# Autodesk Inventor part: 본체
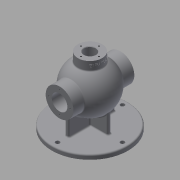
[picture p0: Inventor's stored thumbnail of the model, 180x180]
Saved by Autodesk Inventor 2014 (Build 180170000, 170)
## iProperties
Created: 2020-08
Part Number: 본체
Material: Generic
Document SubType Name: Modeling
Designer: kh
Density: 1 g/cm^3
Appearance: Default
Author: kh
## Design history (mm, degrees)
sketch "Sketch1"
  geometry: C1 r 85 at (0, 0); 1 further point
  constraints: 1 centre point, 1 coincident
  dimensions: "d0" = 170 diameter of C1
extrude "Extrusion1" new body sketch "Sketch1" distance "d1" = 10; taper "d2" = 0 deg
sketch "Sketch2"
  geometry: L1 (85, 10)-(85, 0) reference; L2 (85, 0)-(-85, 0) reference; L3 (-85, 0)-(-85, 10) reference; L4 (-85, 10)-(85, 10) reference; L5 (85, 10)-(85, 0) reference; L6 (85, 0)-(-85, 0) reference; L7 (-85, 0)-(-85, 10) reference; L8 (-85, 10)-(85, 10) reference; L9 (0, 0)-(0, 85); L10 (-68, 85)-(68, 85); L11 (42.988, 116)-(68, 116); L12 (0, 85)-(0, 138); L13 (68, 116)-(68, 102.5); L14 (68, 102.5)-(39.278, 102.5); L15 (-42.988, 116)-(-68, 116); L16 (-68, 116)-(-68, 102.5); L17 (-68, 102.5)-(-39.278, 102.5); A1 r 53 centre (0, 85) between (42.988, 116) and (0, 138); A2 r 43 centre (0, 85) between (39.278, 102.5) and (0, 128); A3 r 43 centre (0, 85) between (0, 128) and (-39.278, 102.5); A4 r 53 centre (0, 85) between (0, 138) and (-42.988, 116)
  constraints: 18 end point, 8 point on circle, 4 centre point, 4 perpendicular, 4 symmetric about line, 3 coincident, 2 parallel, 1 midpoint, 1 point on line, 1 vertical alignment, 2 other
  dimensions: "d3" = 85 distance of L9.end L9.start; "d4" = 53 radius of A1; "d5" = 43 radius of A2; "d7" = 62 diameter of L11.end L10; "d8" = 35 diameter of L13.end L10; "d9" = 136 distance of L10.start L10.end
revolve "Revolution1" sketch "Sketch2" stored, may be unused: angle "d15" = 90 deg
workplane "Work Plane1"
sketch "Sketch4"
  geometry: L1 (31, -42.988)-(-31, -42.988) reference; L2 (31, 42.988)-(-31, 42.988) reference; C1 r 27 at (0, 0); A1 r 53 centre (0, 0) between (-31, 42.988) and (31, 42.988) reference; 1 further point
  constraints: 1 centre point, 1 coincident
  dimensions: "d25" = 54 diameter of C1
extrude "Extrusion2" join sketch "Sketch4" stored distance "d26" = 10; taper "d27" = 0 deg
sketch "Sketch5"
  geometry: C1 r 27 at (0, 0) reference; C2 r 13 at (0, 0); 1 further point
  constraints: 1 centre point, 1 coincident
  dimensions: "d28" = 26 diameter of C2
extrude "Extrusion3" cut sketch "Sketch5" stored distance "d29" = 10; taper "d30" = 0 deg
sketch "Sketch6"
  geometry: L1 (0, 27)-(0, -27); L2 (27, 0)-(-27, 0); C1 r 13 at (0, 0) reference; A1 r 27 centre (0, 0) between (0, 27) and (0, -27) reference; A2 r 20 centre (0, 0) between (20, 0) and (0, 20); 6 further points
  constraints: 7 point on circle, 5 midpoint, 4 end point, 4 point on line, 1 centre point, 1 coincident, 1 horizontal, 1 horizontal alignment, 1 vertical, 1 other
  dimensions: "d31" = 40 diameter of A2
hole "Hole1" sketch "Sketch6" at (20, 0), (0, 20), (-20, 0), (0, -20) diameter "d32" = 3.242; stored, may be unused: countersink angle "d36" = 90 deg, drill point angle "d38" = 118 deg; dims "d33" = 12, "d34" = 4, "d35" = 2, "d37" = 15
sketch "Sketch7"
  geometry: L1 (-51, -85)-(-51, -75) reference; L2 (-51, -75)-(51, -75) reference; L3 (51, -75)-(51, -85) reference; L4 (51, -85)-(-51, -85) reference; L5 (0, 31)-(0, -31); L6 (-31, 0)-(31, 0); C1 r 17.5 at (0, 0) reference; A1 r 31 centre (0, 0) between (0, 31) and (0, -31) reference; A2 r 24 centre (0, 0) between (-24, 0) and (0, 24); 5 further points
  constraints: 8 point on circle, 4 end point, 4 midpoint, 4 point on line, 2 perpendicular, 1 centre point, 1 coincident
  dimensions: "d39" = 48 diameter of A2
hole "Hole2" sketch "Sketch7" at (-24, 0), (0, 24), (24, 0), (0, -24) diameter "d40" = 3.242; stored, may be unused: countersink angle "d44" = 90 deg, drill point angle "d46" = 118 deg; dims "d41" = 12, "d42" = 4, "d43" = 2, "d45" = 15
mirror "Mirror1"
sketch "Sketch8"
  geometry: L1 (-4, 52)-(4, 52); L2 (4, 52)-(4, -52); L3 (4, -52)-(-4, -52); L4 (-4, -52)-(-4, 52); L5 (-4, 52)-(4, -52); L6 (4, 52)-(-4, -52); L7 (-43, 4)-(43, 4); L8 (43, 4)-(43, -4); L9 (43, -4)-(-43, -4); L10 (-43, -4)-(-43, 4); L11 (-43, 4)-(43, -4); L12 (43, 4)-(-43, -4); C1 r 85 at (0, 0) reference
  constraints: 24 end point, 4 midpoint, 4 parallel, 2 horizontal, 2 perpendicular
  dimensions: "d49" = 8 distance of L2.end L3.end; "d50" = 104 distance of L1.end L2.end; "d51" = 86 distance of L8.end L9.end; "d52" = 8 distance of L7.end L8.end
extrude "Extrusion4" join sketch "Sketch8" stored distance "d53" = 10; taper "d54" = 0 deg
sketch "Sketch9"
  geometry: L1 (-43, 4)-(-4, 4) reference; L2 (-4, 4)-(-4, 52) reference; L3 (-4, 52)-(4, 52) reference; L4 (4, 52)-(4, 4) reference; L5 (4, 4)-(43, 4) reference; L6 (43, 4)-(43, -4) reference; L7 (43, -4)-(4, -4) reference; L8 (4, -4)-(4, -52) reference; L9 (4, -52)-(-4, -52) reference; L10 (-4, -52)-(-4, -4) reference; L11 (-4, -4)-(-43, -4) reference; L12 (-43, -4)-(-43, 4) reference; L13 (0, 85)-(0, -85); L14 (85, 0)-(-85, 0); C1 r 4.5 at (0, 72.5); C2 r 4.5 at (72.5, 0); C3 r 4.5 at (0, -72.5); C4 r 4.5 at (-72.5, 0); A1 r 85 centre (0, 0) between (0, 85) and (0, -85) reference; A2 r 72.5 centre (0, 0) between (0, 72.5) and (72.5, 0); 2 further points
  constraints: 8 point on circle, 5 centre point, 4 end point, 4 point on line, 3 equal radius, 3 midpoint, 2 parallel, 1 coincident
  dimensions: "d55" = 145 diameter of A2; "d56" = 9 diameter of C1
extrude "Extrusion5" cut sketch "Sketch9" stored distance "d57" = 10; taper "d58" = 0 deg
workplane "Work Plane2"
sketch "Sketch10"
  geometry: L1 (-59.206, -31.786)-(59.206, -31.786); L2 (59.206, -31.786)-(59.206, 13.786); L3 (59.206, 13.786)-(-59.206, 13.786); L4 (-59.206, 13.786)-(-59.206, -31.786); L5 (-59.206, -31.786)-(59.206, 13.786); L6 (59.206, -31.786)-(-59.206, 13.786); L7 (-27, 0)-(-27, -19.393) reference; L8 (-27, 0)-(27, 0) reference; L9 (27, 0)-(27, -19.393) reference; L10 (-27, -19.393)-(27, -19.393) reference; 2 further points
  constraints: 4 end point, 1 midpoint, 2 other
  dimensions: "d59" = 9 distance from line of L8 point (0, -9); "d60" = 27 distance from line of L7 point (0, -9)
emboss "Emboss1" sketch "Sketch10" dims "d61" = 0.5, "d62" = 0
fillet "Fillet1" dims "d63" = 3
fillet "Fillet2" dims "d64" = 3
fillet "Fillet3" dims "d65" = 3
fillet "Fillet4" dims "d66" = 3
chamfer "Chamfer1" distance "d67" = 1; stored, may be unused: second distance "d68" = 2, angle "d69" = 45 deg
sketch "Sketch11"
  geometry: L1 (85, 7)-(85, 0) reference; L2 (85, 0)-(77, 0) reference; L3 (77, 0)-(77, 10) reference; L4 (77, 10)-(82, 10) reference; L5 (-82, 10)-(-77, 10) reference; L6 (-77, 10)-(-77, 0) reference; L7 (-77, 0)-(-85, 0) reference; L8 (-85, 0)-(-85, 7) reference; L9 (-52.026, 61)-(-53, 62.621) reference; L10 (-53, 62.621)-(-68, 62.621) reference; L11 (-68, 62.621)-(-68, 67.5) reference; L12 (-68, 67.5)-(-39.278, 67.5) reference; L13 (39.278, 67.5)-(68, 67.5) reference; L14 (68, 67.5)-(68, 62.621) reference; L15 (68, 62.621)-(53, 62.621) reference; L16 (53, 62.621)-(52.026, 61) reference; L17 (52.026, 61)-(53, 59.379) reference; L18 (53, 59.379)-(68, 59.379) reference; L19 (68, 59.379)-(68, 54) reference; L20 (68, 54)-(55, 54) reference; L21 (52, 51)-(52, 13) reference; L22 (55, 10)-(68, 10) reference; L23 (68, 10)-(68, 0) reference; L24 (68, 0)-(-68, 0) reference; L25 (-68, 0)-(-68, 10) reference; L26 (-68, 10)-(-55, 10) reference; L27 (-52, 13)-(-52, 51) reference; L28 (-55, 54)-(-68, 54) reference; L29 (-68, 54)-(-68, 59.379) reference; L30 (-68, 59.379)-(-53, 59.379) reference; L31 (-53, 59.379)-(-52.026, 61) reference; L32 (20, 134.026)-(21.621, 135) reference; L33 (21.621, 135)-(21.621, 150) reference; L34 (21.621, 150)-(27, 150) reference; L35 (27, 150)-(27, 132.286) reference; L36 (44.497, 116)-(68, 116) reference; L37 (68, 116)-(68, 110.621) reference; L38 (68, 110.621)-(53, 110.621) reference; L39 (53, 110.621)-(52.026, 109) reference; L40 (52.026, 109)-(53, 107.379) reference; L41 (53, 107.379)-(68, 107.379) reference; L42 (68, 107.379)-(68, 102.5) reference; L43 (68, 102.5)-(39.278, 102.5) reference; L44 (13, 125.988)-(13, 149) reference; L45 (13, 149)-(14, 150) reference; L46 (14, 150)-(18.379, 150) reference; L47 (18.379, 150)-(18.379, 135) reference; L48 (18.379, 135)-(20, 134.026) reference; L49 (-20, 134.026)-(-18.379, 135) reference; L50 (-18.379, 135)-(-18.379, 150) reference; L51 (-18.379, 150)-(-14, 150) reference; L52 (-14, 150)-(-13, 149) reference; L53 (-13, 149)-(-13, 125.988) reference; L54 (-39.278, 102.5)-(-68, 102.5) reference; L55 (-68, 102.5)-(-68, 107.379) reference; L56 (-68, 107.379)-(-53, 107.379) reference; L57 (-53, 107.379)-(-52.026, 109) reference; L58 (-52.026, 109)-(-53, 110.621) reference; L59 (-53, 110.621)-(-68, 110.621) reference; L60 (-68, 110.621)-(-68, 116) reference; L61 (-68, 116)-(-44.497, 116) reference; L62 (-27, 132.286)-(-27, 150) reference; L63 (-27, 150)-(-21.621, 150) reference; L64 (-21.621, 150)-(-21.621, 135) reference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; A1 r 3 centre (82, 7) between (85, 7) and (82, 10) reference; A2 r 3 centre (-82, 7) between (-82, 10) and (-85, 7) reference; A3 r 43 centre (0, 85) between (-39.278, 67.5) and (39.278, 67.5) reference; A4 r 3 centre (55, 51) between (55, 54) and (52, 51) reference; A5 r 3 centre (55, 13) between (52, 13) and (55, 10) reference; A6 r 3 centre (-55, 13) between (-55, 10) and (-52, 13) reference; A7 r 3 centre (-55, 51) between (-52, 51) and (-55, 54) reference; A8 r 3 centre (30, 132.286) between (27, 132.286) and (28.393, 129.753) reference; A9 r 53 centre (0, 85) between (42.113, 117.179) and (28.393, 129.753) reference; A10 r 3 centre (44.497, 119) between (42.113, 117.179) and (44.497, 116) reference; A11 r 43 centre (0, 85) between (39.278, 102.5) and (13, 125.988) reference; A12 r 43 centre (0, 85) between (-13, 125.988) and (-39.278, 102.5) reference; A13 r 3 centre (-44.497, 119) between (-44.497, 116) and (-42.113, 117.179) reference; A14 r 53 centre (0, 85) between (-28.393, 129.753) and (-42.113, 117.179) reference; A15 r 3 centre (-30, 132.286) between (-28.393, 129.753) and (-27, 132.286) reference; 1 further point
  constraints: 8 end point, 3 perpendicular, 2 midpoint, 2 point on line
  dimensions: "d72" = 16 distance between parallel lines of L66 L71; "d73" = 1.75 distance of L69.end L70.end; "d74" = 37 diameter of L69.end L68
revolve "Revolution3" sketch "Sketch11" stored, may be unused: angle "d75" = 90 deg
body "Solid1"
node "Projected Loop1"
node "Project Cut Edges1"
node "Project Cut Edges2"
node "Project Cut Edges4"
node "Project Cut Edges5"
node "Project Cut Edges6"
node "Project Cut Edges7"
node "Project Cut Edges8"
node "Project Cut Edges9"
